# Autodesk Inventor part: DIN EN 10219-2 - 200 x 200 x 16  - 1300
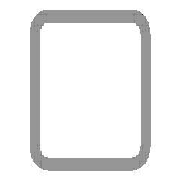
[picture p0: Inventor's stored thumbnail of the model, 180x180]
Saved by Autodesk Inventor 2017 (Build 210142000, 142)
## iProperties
Created: 2017-11
Part Number: DIN EN 10219-2 - 200 x 200 x 16  - 1300
Material: Steel, Mild
Description: Cold formed welded structural hollow sections of non-alloy and fine grain structural steel
Document SubType Name: Modeling
Standard: DIN
Designer: iusti
Standard Revision: 2006-07
Standards Organization: DIN
Language: en-US
Size Designation: 200 x 200 x 16
Categories: <MemberInstance><Categories><Category DisplayName="Structural Shapes" InternalName="089c4875-fa83-4c05-b084-43b9cc11f5ed" Mnemonic="GRDR"><CategoryParameter Dis
Stock Number: 200 x 200 x 16
Mass: 108961 g
Surface Area: 17564.1 cm^2
Volume: 13880.4 cm^3
Density: 7.85 g/cm^3
Appearance: Semi-Polished
_CCFamilyMember: 103
_CCFamilyDisplayName: DIN EN 10219-2 (Square Hollow Section - Cold Formed) - Cold formed welded structural hollow sections of non-alloy and fine grain structural steel
_FrameMemberDoc: Frame Member File
_Version: 15.0.0
_GetPNFromCC: 1
G_L: 1300.000 mm
G_W: 200.000 mm
G_H: 200.000 mm
+E3F72FB6-EDBE-4075-8A55-21F95EDF68B6+CUTDETAIL1: Cut
+0D64326D-6ACF-4319-9054-E2A081320EBA+CUTDETAIL2: Cut
IsCustomPart: 1
Author: iusti
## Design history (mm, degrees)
node "Start plane"
node "End plane"
sketch "Sketch"
  geometry: L1 (-100, -52)-(-100, 52); L2 (-52, 100)-(52, 100); L3 (100, 52)-(100, -52); L4 (52, -100)-(-52, -100); L5 (-52, 84)-(52, 84); L6 (84, 52)-(84, -52); L7 (52, -84)-(-52, -84); L8 (-84, -52)-(-84, 52); L9 (0, 153.918)-(0, -153.918) reference; L10 (-153.918, 0)-(153.918, 0) reference; A1 r 48 centre (-52, -52) between (-100, -52) and (-52, -100); A2 r 48 centre (-52, 52) between (-52, 100) and (-100, 52); A3 r 48 centre (52, 52) between (100, 52) and (52, 100); A4 r 48 centre (52, -52) between (52, -100) and (100, -52); A5 r 32 centre (-52, 52) between (-52, 84) and (-84, 52); A6 r 32 centre (52, 52) between (84, 52) and (52, 84); A7 r 32 centre (52, -52) between (52, -84) and (84, -52); A8 r 32 centre (-52, -52) between (-84, -52) and (-52, -84)
  constraints: 16 end point, 16 point on circle, 8 centre point, 8 tangent, 4 parallel, 3 equal radius, 2 perpendicular, 7 other
  dimensions: "d7" = 48 radius of A1 (= G_IR); "d10" = 200 distance between parallel lines of L2 L4 (= G_H); "d11" = 200 distance between parallel lines of L1 L3 (= G_W); "d12" = 16 distance between parallel lines of L3 L6 (= G_T); "d15" = 100 distance between parallel lines of L2 L10 (= 0.5 x d10); "d16" = 100 distance between parallel lines of L9 L3 (= 0.5 x d11)
extrude "Body" new body sketch "Sketch" stored distance "d3" = 1300 (= G_L); taper "d4" = 0 deg
node "Driven Length"
  sketch "Sketch3"
    geometry: L1 (0, 0)-(10, 0) reference
    constraints: 2 end point, 1 horizontal
  workplane "Work Plane3"
  sketch "Sketch4"
    geometry: L1 (-2, 100)-(12, 100) reference; L2 (-2, 1400)-(12, 1400) reference
    dimensions: "d18" = 1300 distance between parallel lines of L1 L2 (derived)
workplane "Work Plane4"
split "Split1"
workplane "Work Plane5"
split "Split2"
body "Solid1"
other parameters: "G_W" = 200 [user parameter; used in 1 equation term], "G_H" = 200 [user parameter; used in 1 equation term], "G_T" = 16 [user parameter; used in 1 equation term], "G_IR" = 48 [user parameter; used in 1 equation term], "G_L" = 1300 (= d18) [user parameter; used in 1 equation term], "d17" = 90 deg
